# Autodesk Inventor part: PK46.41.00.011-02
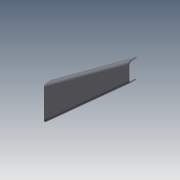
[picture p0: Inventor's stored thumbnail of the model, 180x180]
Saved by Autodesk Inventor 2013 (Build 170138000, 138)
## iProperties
Created: 2005-07
Part Number: PK46.41.00.011-02
Material: Steel, Mild
Document SubType Name: Листовой материал
Designer: tedescj
Manufacturer: Standard
Standards Organization: Custom
Mass: 1058.63 g
Surface Area: 929.402 cm^2
Volume: 134.686 cm^3
Density: 7.86 g/cm^3
Author: PVitaliy
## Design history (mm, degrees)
derived "PK46.41.00.011-01.ipt"
feature "Solid1::PK46.41.00.011-01.ipt" dims "d0" = 10
tag "TaggingFeature1"
body "Solid1"
other parameters: "Thickness" = 3.048, "BendRadius" = 3.048 (= Thickness), "BendReliefWidth" = 3.048 (= Thickness), "BendReliefDepth" = 1.524 (= 0.5 x Thickness), "CornerReliefSize" = 12.192 (= 4 x Thickness), "SeamGap" = 0.00508, "MinimumRemnant" = 6.096 (= 2 x Thickness), "TransitionRadius" = 3.048 (= BendRadius), "JacobiRadiusSize" = 3.048 (= BendRadius), "GapSize" = 3.048 (= Thickness)
